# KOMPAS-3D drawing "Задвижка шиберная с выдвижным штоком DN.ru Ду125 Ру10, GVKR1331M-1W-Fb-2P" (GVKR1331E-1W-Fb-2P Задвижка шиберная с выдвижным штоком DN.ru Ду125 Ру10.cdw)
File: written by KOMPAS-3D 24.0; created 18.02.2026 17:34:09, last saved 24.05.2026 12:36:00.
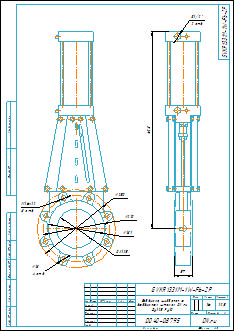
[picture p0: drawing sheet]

Document properties: Автор: R2D2; Форматы листов документа: A3; Полное имя файла: GVKR1331E-1W-Fb-2P Задвижка шиберная с выдвижным штоком DN.ru Ду125 Ру10.m3d; Масса: 16; Наименование: Задвижка шиберная с выдвижным штоком DN.ru Ду125 Ру10; Количество листов документа: 1; Примечание: D040-08795

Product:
- Part/product: Задвижка шиберная с выдвижным штоком DN.ru Ду125 Ру10  | designation GVKR1331M-1W-Fb-2P
    Масса: 16
    Раздел спецификации: Прочие изделия
    Примечание: D040-08795

Views: Вид 1, Спереди, Проекционный вид 2
Referenced files in E:\Работа\Зайцев\GVKR1331N-2W-Fb-S Задвижка шиберная с выдвижным штоком DN.ru Ду50-300 Ру10\DN50\: GVKR1331N-2W-Fb-S Задвижка шиберная DN.ru Ду50 Ру10.m3d
Referenced files in E:\Работа\Зайцев\GVKR1331E-1W-Fb-2P Задвижка шиберная DN.ru Ду50-300 Ру16-10-6\исходные материалы\DN125\DN125\: GVKR1331E-1W-Fb-2P Задвижка шиберная с выдвижным штоком DN.ru Ду125 Ру10.m3d
Referenced files in E:\Работа\Зайцев\Для компаса\: чертеж DN.ru А3.cdt
Referenced files in E:\Работа\Зайцев\GVKR1331M-1W-Fb-2P Задвижка шиберная с выдвижным штоком DN.ru Ду50-300 Ру16-10-6 с пневмоприводом\исходные материалы\DN125\DN125\: GVKR1331E-1W-Fb-2P Задвижка шиберная с выдвижным штоком DN.ru Ду125 Ру10.m3d
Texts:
  GVKR1331M-1W-Fb-2P
  чертеж DN.ru А3.cdt
  Задвижка шиберная с
  выдвижным штоком DN.ru
  Ду125 Ру10
  Задвижка шиберная с выдвижным штоком DN.ru Ду125 Ру10
  GVKR1331M-1W-Fb-2P Задвижка шиберная с выдвижным штоком DN.ru Ду125 Ру10
Dimensions and other numbers on the sheet: 0; 3; 2; 4; 16; 8 отв.; 18; 4 отв.; 250; 181; 210; 125; 2 отв.; 57; 628; 1:2,5; 1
